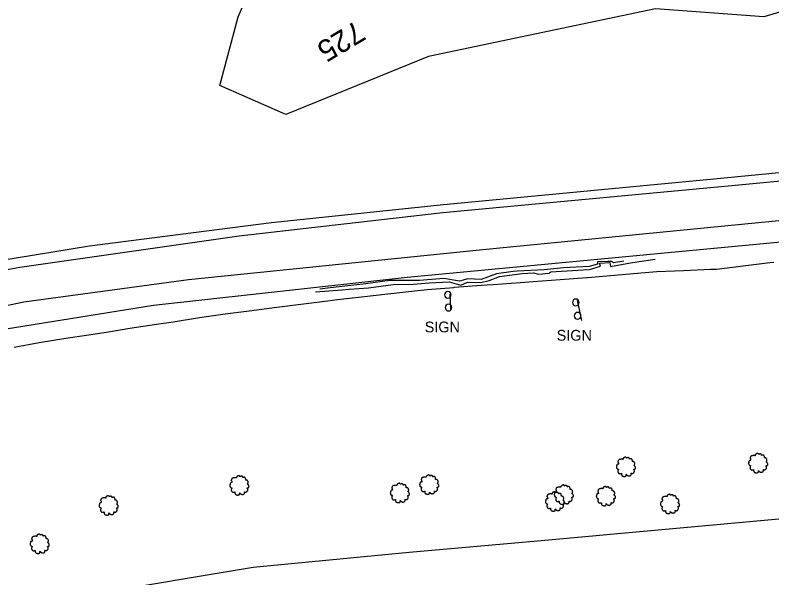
# Model space of a CAD drawing. Extents: x 1901471 to 1963503, y 756461 to 799997.
# Drawn here: x 1911272.8 to 1911553.6, y 761022.6 to 761231.5 of the extents above; entities that cross this region are included whole.
import ezdxf

# ---------------------------------------------------------------- set-up
doc = ezdxf.new("R2010")
doc.units = 0
for name, color, linetype in [('Default', 7, 'Continuous'), ('RD_DTM_BkLn1', 7, 'Continuous'), ('RD_EX_Bldg', 7, 'Continuous'), ('RD_EX_Fence_Other', 7, 'Continuous'), ('RD_EX_Road', 7, 'Continuous'), ('RD_EX_VEG', 7, 'Continuous'), ('RD_HC_Cl', 7, 'Continuous'), ('RD_HC_TX_Sta50', 7, 'Continuous')]:
    doc.layers.add(name, color=color, linetype=linetype)

# ---------------------------------------------------------------- blocks, each defined once
blk = doc.blocks.new('T2')
at = {"layer": 'RD_EX_VEG'}
for points in [[(0.05233333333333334, 7.213166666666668), (-0.24750000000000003, 7.238166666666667), (-0.5723333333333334, 7.138166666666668), (-0.8222500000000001, 7.038250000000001), (-1.0471666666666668, 6.963250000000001), (-1.2720833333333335, 6.863250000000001), (-1.5719166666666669, 6.688416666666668), (-1.7968333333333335, 6.488416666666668), (-1.9218333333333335, 6.2385833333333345), (-1.9718333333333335, 6.013666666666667), (-2.0217500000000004, 5.738833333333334), (-2.0217500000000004, 5.563833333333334), (-2.146666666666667, 5.538833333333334), (-2.296666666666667, 5.563833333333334), (-2.5465000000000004, 5.638833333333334), (-2.796416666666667, 5.638833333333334), (-3.0463333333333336, 5.638833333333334), (-3.3961666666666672, 5.613833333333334), (-3.7460000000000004, 5.613833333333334), (-4.020833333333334, 5.563833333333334), (-4.345750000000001, 5.513916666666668), (-4.720583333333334, 5.389000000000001), (-5.0704166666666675, 5.264000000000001), (-5.37025, 5.014083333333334), (-5.620166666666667, 4.539333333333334), (-5.745166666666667, 4.189500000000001), (-5.895083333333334, 3.9395833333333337), (-5.745166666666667, 3.489833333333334), (-5.570166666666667, 3.139916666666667), (-5.545250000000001, 2.9400000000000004), (-5.470250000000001, 2.5152500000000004), (-5.37025, 2.2903333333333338), (-5.245333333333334, 2.0903333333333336), (-5.320250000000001, 2.065416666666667), (-5.695166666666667, 2.015416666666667), (-5.995000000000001, 1.9155000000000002), (-6.419833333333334, 1.6905833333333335), (-6.644750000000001, 1.465666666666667), (-6.744750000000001, 1.1407500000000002), (-6.769666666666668, 0.7909166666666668), (-6.869583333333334, 0.5910833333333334), (-6.944583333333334, 0.3161666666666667), (-6.969583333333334, 0.2411666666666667), (-7.019583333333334, -0.08366666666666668), (-6.9195833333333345, -0.5335000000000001), (-6.894583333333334, -0.8833333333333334), (-6.769666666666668, -1.1082500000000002), (-6.619750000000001, -1.2830833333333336), (-6.444833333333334, -1.5330000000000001), (-6.045000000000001, -1.7579166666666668), (-5.7201666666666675, -1.8579166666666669), (-5.520250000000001, -1.8828333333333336), (-5.695166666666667, -2.382666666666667), (-5.745166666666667, -2.7325000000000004), (-5.870083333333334, -3.132333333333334), (-5.870083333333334, -3.2072500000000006), (-5.920000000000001, -3.682083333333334), (-5.770166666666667, -4.007000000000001), (-5.695166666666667, -4.38175), (-5.520250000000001, -4.606666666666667), (-5.245333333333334, -4.906583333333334), (-4.9205000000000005, -5.131416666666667), (-4.420666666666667, -5.256416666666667), (-4.020833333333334, -5.231416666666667), (-3.4460833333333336, -5.056500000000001), (-3.1962500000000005, -4.9815000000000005), (-3.2212500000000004, -5.156416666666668), (-3.1962500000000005, -5.531333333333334), (-3.1962500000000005, -5.956083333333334), (-3.0463333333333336, -6.280916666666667), (-2.946333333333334, -6.555833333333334), (-2.796416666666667, -6.805750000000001), (-2.4715000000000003, -7.030583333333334), (-2.07175, -7.1055833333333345), (-1.6469166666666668, -7.2555000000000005), (-1.1970833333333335, -7.330500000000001), (-0.6973333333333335, -7.355500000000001), (-0.09758333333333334, -7.205583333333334), (0.17725000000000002, -7.080583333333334), (0.27725000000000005, -6.905666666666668), (0.47716666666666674, -6.530833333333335), (0.4271666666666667, -6.3059166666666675), (0.4521666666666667, -5.706166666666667), (0.5520833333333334, -5.881166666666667), (0.7270833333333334, -6.231000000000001), (1.2268333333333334, -6.530833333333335), (1.626666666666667, -6.705750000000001), (2.101416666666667, -6.8557500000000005), (2.4013333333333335, -6.930666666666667), (2.8760833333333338, -6.8557500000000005), (3.2510000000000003, -6.780750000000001), (3.6257500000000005, -6.655750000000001), (3.9256666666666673, -6.380916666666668), (4.100583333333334, -6.106000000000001), (4.1505833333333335, -5.831166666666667), (4.2255, -5.456333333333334), (4.275500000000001, -5.281416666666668)], [(4.275500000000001, -5.281416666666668), (4.200583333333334, -5.106416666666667), (4.1505833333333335, -4.856583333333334), (4.2255, -4.881583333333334), (4.4004166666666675, -4.931583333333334), (4.675333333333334, -5.056500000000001), (4.900250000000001, -5.131416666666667), (5.225083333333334, -5.106416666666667), (5.500000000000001, -5.006500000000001), (5.949750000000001, -4.731583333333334), (6.224666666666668, -4.256833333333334), (6.499500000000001, -3.8570000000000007), (6.5745000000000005, -3.5321666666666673), (6.524500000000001, -3.3072500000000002), (6.499500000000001, -2.8075000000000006), (6.299583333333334, -2.5575833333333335), (6.249583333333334, -2.432666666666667), (6.1496666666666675, -2.0328333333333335), (6.224666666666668, -1.9828333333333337), (6.499500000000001, -1.9328333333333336), (6.874333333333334, -1.8079166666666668), (7.149250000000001, -1.6830000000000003), (7.374166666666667, -1.5080000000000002), (7.449083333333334, -1.2830833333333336), (7.424166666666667, -0.8833333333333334), (7.4740833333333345, -0.48350000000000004), (7.399166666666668, -0.3335), (7.299166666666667, -0.1836666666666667), (7.224166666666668, 0.016333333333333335), (7.074250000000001, 0.16616666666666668), (6.974333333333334, 0.3161666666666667), (6.874333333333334, 0.41608333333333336), (6.749416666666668, 0.5660833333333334), (6.5745000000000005, 0.6910000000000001), (6.424583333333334, 0.7410000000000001), (6.374583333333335, 0.8909166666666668), (6.524500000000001, 1.0908333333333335), (6.5745000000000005, 1.1907500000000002), (6.599416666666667, 1.4156666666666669), (6.824416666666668, 1.7655000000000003), (6.874333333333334, 2.1653333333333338), (6.824416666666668, 2.590166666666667), (6.774416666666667, 2.8650833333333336), (6.624416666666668, 3.139916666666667), (6.424583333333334, 3.3898333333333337), (6.299583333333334, 3.5647500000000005), (6.124666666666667, 3.689666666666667), (5.799833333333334, 3.814666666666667), (5.549916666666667, 3.864583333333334), (5.200083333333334, 3.864583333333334), (5.000166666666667, 3.9145833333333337), (5.025166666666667, 3.964583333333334), (5.025166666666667, 4.1145000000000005), (5.025166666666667, 4.389416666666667), (4.950166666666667, 4.839166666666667), (4.800250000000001, 5.339), (4.800250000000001, 5.364000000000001), (4.7002500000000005, 5.613833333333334), (4.475416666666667, 5.813750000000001), (4.3005, 5.913666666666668), (4.100583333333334, 6.038666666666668), (3.850666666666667, 6.063666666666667), (3.5508333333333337, 6.063666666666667), (3.2759166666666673, 6.013666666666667), (3.0760000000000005, 5.913666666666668), (2.9010833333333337, 5.788750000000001), (2.8260833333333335, 5.938666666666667), (2.726166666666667, 6.2385833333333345), (2.676166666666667, 6.3885000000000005), (2.52625, 6.563416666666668), (2.301416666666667, 6.7633333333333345), (1.8515000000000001, 6.888250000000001), (1.2268333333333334, 6.813333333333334), (0.9269166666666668, 6.613416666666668), (0.7770000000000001, 6.438500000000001), (0.7270833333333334, 6.563416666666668), (0.5270833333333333, 6.7633333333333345), (0.4271666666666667, 6.938250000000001), (0.25225000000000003, 7.063250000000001), (0.10233333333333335, 7.163166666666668), (0.0023333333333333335, 7.213166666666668)]]:
    blk.add_spline(points, degree=3, dxfattribs=at)
blk = doc.blocks.new('SIGNPOST')
at = {"layer": 'Default'}
for centre, start, end in [((7.776250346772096e-18, 0), 90.00000000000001, 270), ((-7.776250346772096e-18, 0), 270, 90)]:
    blk.add_arc(centre, 0.12700000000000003, start, end, dxfattribs=at)

msp = doc.modelspace()

# ---------------------------------------------------------------- linework, layer by layer
at = {"layer": 'RD_DTM_BkLn1'}
for points in [[(1911272.4510642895, 761108.2306744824), (1911281.7787249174, 761110.0406444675), (1911291.6564016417, 761111.5758980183), (1911297.5404044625, 761112.4904284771), (1911307.41294954, 761114.0353918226), (1911315.361504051, 761115.2792681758), (1911325.2392874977, 761116.7814676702), (1911331.403334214, 761117.7188872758), (1911341.2816714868, 761119.2368782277), (1911350.716227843, 761120.686673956), (1911360.630919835, 761121.9212606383), (1911368.8832563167, 761122.9488492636), (1911378.794309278, 761124.2248754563), (1911388.7053622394, 761125.5009016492), (1911392.4918420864, 761125.9884025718), (1911402.419080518, 761127.1065118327), (1911410.0655319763, 761127.9677350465), (1911419.9990991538, 761129.0434998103), (1911425.6825036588, 761129.6589893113), (1911435.6292329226, 761130.4755849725), (1911435.8399790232, 761130.4928865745), (1911445.8049559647, 761131.2369348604), (1911450.2459062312, 761131.5685243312), (1911460.2057816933, 761132.3285175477), (1911465.086859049, 761132.7009705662), (1911475.052525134, 761133.4166124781), (1911485.0181912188, 761134.1322543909), (1911485.241104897, 761134.1482619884), (1911495.1956204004, 761135.0149386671), (1911505.1501359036, 761135.8816153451), (1911510.9049275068, 761136.3826486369), (1911520.8830518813, 761136.7923425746), (1911530.8611762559, 761137.2020365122), (1911533.0320387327, 761137.2911704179), (1911542.9534507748, 761138.493472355), (1911552.8748628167, 761139.6957742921), (1911554.3370820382, 761139.8729697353)], [(1911384.2522088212, 761128.8727090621), (1911394.2235563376, 761129.576423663), (1911396.77153, 761129.756243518), (1911403.9546857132, 761130.301910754), (1911413.0663044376, 761131.550201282), (1911420.5790939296, 761131.713166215), (1911426.484829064, 761132.1003675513), (1911433.9213761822, 761132.5914702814), (1911438.2252934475, 761131.3536749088), (1911440.657548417, 761132.3792050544), (1911445.578123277, 761132.2812981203), (1911448.704626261, 761132.9767484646), (1911452.6123796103, 761134.5681144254), (1911461.0243697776, 761135.6123448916), (1911465.138427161, 761135.8156652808), (1911467.0310143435, 761135.3866235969), (1911470.9940829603, 761135.7872749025), (1911471.6137319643, 761136.252200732), (1911481.5827879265, 761136.877038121), (1911483.5993620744, 761137.0034323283), (1911485.9254788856, 761137.0901437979), (1911489.9924433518, 761138.3892505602), (1911489.6762623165, 761139.499985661), (1911493.5608473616, 761139.7025580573), (1911493.7081017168, 761138.2233213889), (1911497.1285089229, 761138.8160704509), (1911501.9048202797, 761139.7653643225), (1911510.3085880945, 761140.9045230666)], [(1911498.706408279, 761140.2534529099), (1911494.882817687, 761139.5454435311), (1911494.1778058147, 761140.0218773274), (1911492.8047089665, 761140.0846614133), (1911488.927598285, 761140.0166330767), (1911488.8679524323, 761139.137312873), (1911485.8939330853, 761138.2714404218), (1911476.2782209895, 761137.7637389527), (1911469.1391662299, 761137.0401746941), (1911459.1647964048, 761136.507486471), (1911457.6199551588, 761136.4249831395), (1911451.4114972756, 761135.4472822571), (1911445.6954729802, 761133.421932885), (1911440.755613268, 761133.6099842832), (1911437.7219458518, 761132.8364986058), (1911431.954489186, 761133.7237286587), (1911422.8901090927, 761133.0342444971), (1911412.9020111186, 761132.9786892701), (1911411.8929276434, 761132.9730766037), (1911401.983251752, 761131.6756446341), (1911399.5896260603, 761131.3622573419), (1911389.6614537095, 761130.2449072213), (1911385.9408838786, 761129.8261816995)]]:
    msp.add_lwpolyline(points, dxfattribs=at)
at = {"layer": 'RD_EX_Bldg'}
for points in [[(1911434.4700000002, 761122.5400000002), (1911434.2600000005, 761127.9300000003)], [(1911483.0600000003, 761118.2200000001), (1911481.5500000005, 761125.7800000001)]]:
    msp.add_lwpolyline(points, dxfattribs=at)
at = {"layer": 'RD_EX_Fence_Other'}
msp.add_lwpolyline([(1911301.9000000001, 761016.7600000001), (1911361.1900000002, 761026.56), (1911419.0900000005, 761032.2400000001), (1911466.6600000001, 761036.3500000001), (1911557.6200000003, 761044.6600000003), (1911663.6100000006, 761054.8900000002), (1911770.6600000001, 761064.9500000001), (1911924.9300000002, 761079.7300000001), (1911937.8700000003, 761081.2100000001), (1911956.5900000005, 761082.7900000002), (1911971.6300000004, 761071.4200000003), (1912021.4800000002, 761029.7900000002)], dxfattribs=at)
at = {"layer": 'RD_EX_Road'}
for points in [[(1910806.9500000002, 760986.5100000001), (1910899.8100000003, 761023.81), (1910997.7000000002, 761062.6800000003), (1911080.9600000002, 761091.3600000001), (1911138.0600000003, 761108.1500000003), (1911210.7600000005, 761126.2700000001), (1911274.5800000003, 761138.0200000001), (1911355.9200000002, 761149.6600000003), (1911431.5000000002, 761158.3), (1911541.39, 761168.4900000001), (1911685.3400000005, 761182.2900000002), (1911828.5800000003, 761195.8500000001), (1911899.8400000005, 761202.2000000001), (1911938.9100000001, 761205.6900000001), (1911998.9400000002, 761210.4500000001), (1912025.0700000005, 761212.82)], [(1910882.7900000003, 761021.0400000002), (1910921.3000000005, 761035.5200000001), (1910979.8800000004, 761059.55), (1911049.0000000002, 761083.58), (1911113.1800000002, 761104.9700000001), (1911182.9500000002, 761123.7300000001), (1911238.2500000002, 761135.7400000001), (1911300.4500000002, 761145.9500000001), (1911367.9200000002, 761154.5000000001), (1911431.7700000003, 761161.2500000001), (1911532.1500000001, 761170.7900000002), (1911649.3200000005, 761182.1500000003), (1911779.6600000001, 761194.6600000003), (1911899.7900000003, 761205.6800000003)], [(1910585.7400000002, 760878.06), (1910710.5000000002, 760928.56), (1910888.2900000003, 761001.6200000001), (1910940.6000000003, 761022.7400000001), (1910979.4700000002, 761037.9700000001), (1911045.6900000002, 761063.8800000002), (1911129.1800000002, 761091.6000000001), (1911194.2000000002, 761107.9100000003), (1911276.0200000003, 761125.07), (1911337.2000000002, 761133.4600000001), (1911445.1700000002, 761144.3800000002), (1911566.3400000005, 761156.2600000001), (1911684.3800000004, 761167.8900000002), (1911741.9700000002, 761173.4100000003), (1911807.2300000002, 761177.7300000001), (1911899.39, 761184.4200000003), (1911950.14, 761188.5300000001), (1911980.8000000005, 761190.4700000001), (1911998.7200000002, 761190.6900000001), (1912012.5400000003, 761189.3900000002), (1912024.6300000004, 761186.8)], [(1911898.8000000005, 761179.0200000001), (1911785.9100000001, 761169.1500000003), (1911700.3400000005, 761161.58), (1911583.1700000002, 761149.7300000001), (1911418.2800000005, 761134.1000000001), (1911324.1500000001, 761123.7300000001), (1911252.4000000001, 761112.2100000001), (1911180.9800000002, 761095.7500000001), (1911047.6800000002, 761055.4400000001), (1910980.2100000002, 761027.7900000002), (1910849.6300000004, 760977.0200000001), (1910755.8200000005, 760938.1500000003), (1910677.8100000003, 760906.7700000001), (1910499.5700000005, 760835.6900000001), (1910338.5000000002, 760760.5400000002), (1910201.4000000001, 760696.8700000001), (1909857.8700000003, 760545.9200000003), (1909713.0200000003, 760487.06), (1909551.9400000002, 760422.8900000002), (1909472.4100000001, 760392.4500000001), (1909224.6300000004, 760297.56), (1909135.3400000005, 760263.3900000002), (1909100.5900000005, 760249.4700000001)]]:
    msp.add_lwpolyline(points, dxfattribs=at)
at = {"layer": 'RD_EX_VEG'}
msp.add_lwpolyline([(1911365.4000000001, 761253.4500000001), (1911526.14, 761364.2000000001), (1911737.8400000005, 761511.2200000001), (1911890.7300000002, 761612.1700000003), (1911939.7400000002, 761640.5900000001), (1911963.2600000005, 761618.05), (1911978.9400000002, 761536.7000000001), (1911996.5800000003, 761334.8), (1911908.3700000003, 761317.1600000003), (1911863.2900000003, 761327.9400000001), (1911813.3100000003, 761327.9400000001), (1911783.9000000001, 761303.4400000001), (1911744.7000000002, 761299.5200000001), (1911720.2000000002, 761318.1400000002), (1911700.5900000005, 761325.0000000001), (1911700.5900000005, 761315.2000000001), (1911721.1800000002, 761294.6100000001), (1911606.5100000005, 761247.57), (1911550.64, 761230.9100000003), (1911510.4600000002, 761233.8500000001), (1911426.1700000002, 761216.2100000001), (1911373.2400000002, 761194.6400000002), (1911348.7400000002, 761205.4300000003), (1911355.6000000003, 761230.9100000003)], close=True, dxfattribs=at)
at = {"layer": 'RD_HC_Cl'}
for centre, radius, start, end in [((1905408.2458716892, 771170.6492824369), 11414.0664, 290.894469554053, 304.0088245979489), ((1905390.191717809, 771086.470862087), 11384.366000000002, 290.90340658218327, 304.0085286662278), ((1905358.488046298, 771272.4106571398), 11611.5386, 290.90197060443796, 304.0171003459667)]:
    msp.add_arc(centre, radius, start, end, dxfattribs=at)

# ---------------------------------------------------------------- block references
at = {"layer": 'RD_EX_Bldg', "xscale": 9.84251968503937, "yscale": 9.84251968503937}
for p in [(1911433.39, 761127.7200000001), (1911480.9000000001, 761124.9100000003), (1911433.6100000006, 761122.9700000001), (1911481.5500000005, 761119.9500000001)]:
    msp.add_blockref('SIGNPOST', p, dxfattribs=at)
at = {"layer": 'RD_EX_VEG', "xscale": 0.4921259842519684, "yscale": 0.4921259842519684}
for p in [(1911499.39, 761063.9100000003), (1911548.4300000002, 761065.2700000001), (1911426.3800000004, 761057.2800000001), (1911355.9200000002, 761057.0100000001), (1911415.4900000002, 761054.2000000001), (1911476.3300000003, 761053.56), (1911491.9400000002, 761053.0100000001), (1911307.4300000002, 761049.56), (1911473.0600000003, 761051.0200000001), (1911515.7400000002, 761050.1100000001), (1911281.8200000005, 761035.31)]:
    msp.add_blockref('T2', p, dxfattribs=at)

# ---------------------------------------------------------------- texts
at = {"layer": 'RD_EX_Road'}
for p in [(1911424.8100000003, 761113.7800000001), (1911473.7800000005, 761110.6900000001)]:
    msp.add_text('SIGN', height=4.000000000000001, dxfattribs=at).set_placement(p)
at = {"layer": 'RD_HC_TX_Sta50'}
msp.add_text('725', height=8.000000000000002, rotation=210.98554953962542, dxfattribs=at).set_placement((1911399.4198490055, 761229.7614244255))

doc.saveas('drawing.dxf')
